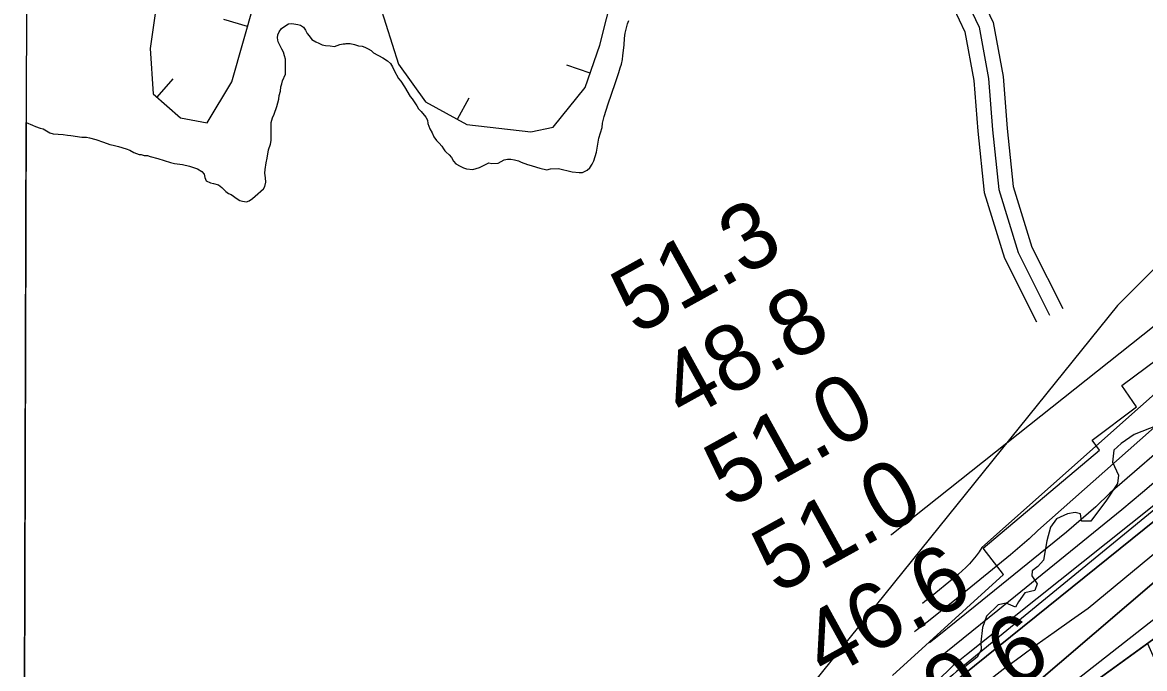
# Model space of a CAD drawing. Extents: x 3177385 to 3215275, y 903885 to 929304.
# Drawn here: x 3181603 to 3182745, y 910081 to 910738 of the extents above; entities that cross this region are included whole.
import ezdxf

# ---------------------------------------------------------------- set-up
doc = ezdxf.new("R2010")
doc.units = 0
for name, color, linetype in [('V-BORW-LINE', 7, 'Continuous'), ('V-GRID-FRAM', 7, 'Continuous'), ('V-RIVR-EDGE', 7, 'Continuous'), ('V-RIVR-RANG', 7, 'Continuous'), ('V-ROAD-CNTR', 7, 'Continuous'), ('V-RRAP-RVMT', 7, 'Continuous'), ('V-SITE-VEGE', 7, 'Continuous'), ('V-TOPO-DPTH', 7, 'Continuous'), ('V-TOPO-MAJR', 7, 'Continuous'), ('V-TOPO-MINR', 7, 'Continuous'), ('V-TOPO-WATR', 7, 'Continuous')]:
    doc.layers.add(name, color=color, linetype=linetype)

msp = doc.modelspace()

# ---------------------------------------------------------------- linework, layer by layer
at = {"layer": 'V-BORW-LINE'}
for p, q in [((3181832.4, 910734), (3181808.4, 910740.9)), ((3182180.7, 910686.3), (3182157.1, 910694.5)), ((3181740.4, 910661.9), (3181756.8, 910680.7)), ((3182045.9, 910639.5), (3182057.7, 910661.5))]:
    msp.add_line(p, q, dxfattribs=at)
for points in [[(3181742.7, 910778.1), (3181733.5, 910711.5)], [(3182190.6, 910714.8), (3182204.3, 910768.7)], [(3181816.3, 910677.6), (3181839.4, 910758.7)], [(3181966.5, 910756.7), (3181985.8, 910695.6)], [(3181733.5, 910711.5), (3181736.3, 910665.4)], [(3182175.7, 910671.8), (3182190.6, 910714.8)], [(3181985.8, 910695.6), (3182013.3, 910657.1)], [(3181791.3, 910635.8), (3181816.3, 910677.6)], [(3182143.2, 910631.6), (3182175.7, 910671.8)], [(3181736.3, 910665.4), (3181764.3, 910641)], [(3182013.3, 910657.1), (3182055.4, 910634.3)], [(3181764.3, 910641), (3181791.3, 910635.8)], [(3182055.4, 910634.3), (3182120.4, 910626.8)], [(3182120.4, 910626.8), (3182143.2, 910631.6)]]:
    msp.add_lwpolyline(points, dxfattribs=at)
at = {"layer": 'V-GRID-FRAM'}
msp.add_lwpolyline([(3181653.7, 927525.9), (3181603.5, 909337.1), (3212939.2, 909264.2), (3212973.6, 927453), (3181653.7, 927525.9)], dxfattribs=at)
at = {"layer": 'V-RIVR-EDGE'}
for points in [[(3182757.3, 910328.2), (3182734.2, 910319.1), (3182720.8, 910309.9), (3182713.4, 910302.9), (3182712, 910290.9), (3182718, 910277.5), (3182717, 910269.2), (3182705.9, 910252.2), (3182690.1, 910230.9), (3182680.4, 910231), (3182679.5, 910238.4), (3182674, 910239.8), (3182666.1, 910238.4), (3182655, 910233.3), (3182649, 910224.6)], [(3182649, 910224.6), (3182645.3, 910210.7), (3182642, 910191.3), (3182636, 910184.9), (3182630.4, 910180.3), (3182629.9, 910175.2), (3182635.5, 910167.3), (3182633.1, 910160.4), (3182623, 910158.1), (3182616.5, 910148.9), (3182613.2, 910143.4), (3182604, 910147.6), (3182595.7, 910145.7), (3182583.7, 910134.2), (3182579.9, 910122.7), (3182578.1, 910107.9), (3182578.5, 910100.1), (3182574.3, 910092.7), (3182557.2, 910078.9)]]:
    msp.add_lwpolyline(points, dxfattribs=at)
at = {"layer": 'V-ROAD-CNTR'}
for points in [[(3182465.1, 912073.3), (3182448.6, 911930.8), (3182431.1, 911826.4), (3182415.3, 911728.9), (3182410.1, 911644.8), (3182407.2, 911570.4), (3182383.2, 911504.1), (3182361.3, 911446.3), (3182341, 911383.3), (3182327.8, 911314.4), (3182322.3, 911236), (3182319.5, 911168.2), (3182337.7, 911105.3), (3182378.7, 911013.4), (3182433.5, 910931.2), (3182484.1, 910856.7), (3182532.9, 910789.7), (3182562, 910728.6), (3182571, 910679.1), (3182575.1, 910627.5), (3182581.5, 910565.1), (3182602.1, 910498.4), (3182634.6, 910433.6)], [(3182480, 912071.6), (3182463.4, 911928.7), (3182445.9, 911823.9), (3182430.3, 911727.3), (3182425, 911644.1), (3182422.1, 911567.5), (3182397.3, 911498.9), (3182375.5, 911441.4), (3182355.6, 911379.6), (3182342.7, 911312.5), (3182337.3, 911235.2), (3182334.6, 911170), (3182351.8, 911110.5), (3182391.9, 911020.7), (3182446, 910939.5), (3182496.3, 910865.3), (3182545.9, 910797.4), (3182576.4, 910733.3), (3182585.9, 910681.1), (3182590.1, 910628.9), (3182596.3, 910568.1), (3182616, 910504), (3182648, 910440.3)], [(3182494.9, 912069.8), (3182478.3, 911926.6), (3182460.7, 911821.5), (3182445.2, 911725.6), (3182440, 911643.3), (3182437, 911564.6), (3182411.3, 911493.7), (3182389.7, 911436.4), (3182370.1, 911375.9), (3182357.6, 911310.5), (3182352.3, 911234.3), (3182349.7, 911171.9), (3182366, 911115.7), (3182405.1, 911028), (3182458.4, 910947.9), (3182508.6, 910874), (3182558.8, 910805.1), (3182590.8, 910737.9), (3182600.8, 910683), (3182605, 910630.2), (3182611.1, 910571.1), (3182630, 910509.6), (3182661.4, 910447.1)]]:
    msp.add_lwpolyline(points, dxfattribs=at)
at = {"layer": 'V-RRAP-RVMT'}
for p, q in [((3182721.5, 910368.8), (3182794.8, 910423.3)), ((3182736.4, 910347.1), (3182721.5, 910368.8)), ((3182691.3, 910313.2), (3182736.4, 910347.1)), ((3182698.8, 910303.2), (3182691.3, 910313.2)), ((3182580.6, 910203.5), (3182698.8, 910303.2)), ((3182601.3, 910176.6), (3182580.6, 910203.5)), ((3182488.3, 910073.8), (3182601.3, 910176.6))]:
    msp.add_line(p, q, dxfattribs=at)
at = {"layer": 'V-SITE-VEGE'}
for p, q in [((3182218.8, 910736.7), (3182220, 910740.1)), ((3181863.3, 910725.5), (3181864.5, 910728.6)), ((3181864.5, 910728.6), (3181866.9, 910731.8)), ((3181866.9, 910731.8), (3181871.3, 910735)), ((3181871.3, 910735), (3181874, 910736.5)), ((3181874, 910736.5), (3181877.4, 910736.8)), ((3181877.4, 910736.8), (3181883.5, 910735.8)), ((3181883.5, 910735.8), (3181886.4, 910735.1)), ((3181886.4, 910735.1), (3181889.3, 910733.2)), ((3181889.3, 910733.2), (3181891.3, 910730.3)), ((3181891.3, 910730.3), (3181893, 910726.9)), ((3182216.4, 910727.2), (3182218.8, 910736.7)), ((3181862.9, 910722.3), (3181863.3, 910725.5)), ((3181863.4, 910718.2), (3181862.9, 910722.3)), ((3181867.1, 910710.7), (3181863.4, 910718.2)), ((3181893, 910726.9), (3181895.2, 910724.5)), ((3181895.2, 910724.5), (3181897.9, 910720.8)), ((3181897.9, 910720.8), (3181901.8, 910718.2)), ((3181901.8, 910718.2), (3181905, 910717)), ((3181905, 910717), (3181908.2, 910715.3)), ((3182215.3, 910714.8), (3182215.7, 910721.9)), ((3182215.7, 910721.9), (3182216.4, 910727.2)), ((3181868.8, 910707.7), (3181867.1, 910710.7)), ((3181869.8, 910704.1), (3181868.8, 910707.7)), ((3181908.2, 910715.3), (3181911.8, 910714.6)), ((3181911.8, 910714.6), (3181916.5, 910714.2)), ((3181916.5, 910714.2), (3181920.8, 910713.5)), ((3181920.8, 910713.5), (3181926.4, 910715.5)), ((3181926.4, 910715.5), (3181929.6, 910716.2)), ((3181929.6, 910716.2), (3181931.8, 910716.2)), ((3181931.8, 910716.2), (3181932.8, 910716.7)), ((3181932.8, 910716.7), (3181936.9, 910716.5)), ((3181936.9, 910716.5), (3181941, 910715.6)), ((3181941, 910715.6), (3181945.2, 910714.1)), ((3181945.2, 910714.1), (3181948.8, 910713.9)), ((3181948.8, 910713.9), (3181951.8, 910713)), ((3181951.8, 910713), (3181955.2, 910711.3)), ((3181955.2, 910711.3), (3181958.1, 910709.6)), ((3181958.1, 910709.6), (3181960.6, 910707.2)), ((3181960.6, 910707.2), (3181970.1, 910701.9)), ((3182213.9, 910704.3), (3182215.3, 910714.8)), ((3181871.1, 910700.5), (3181869.8, 910704.1)), ((3181871.1, 910692.2), (3181871.1, 910700.5)), ((3181970.1, 910701.9), (3181974.7, 910698.8)), ((3181974.7, 910698.8), (3181977.7, 910696.1)), ((3181977.7, 910696.1), (3181979.9, 910692.7)), ((3182211.3, 910691.9), (3182212.7, 910695.6)), ((3182212.7, 910695.6), (3182213.7, 910700.4)), ((3182213.7, 910700.4), (3182213.9, 910704.3)), ((3181868, 910678.5), (3181870.9, 910685.4)), ((3181870.9, 910685.4), (3181871.1, 910692.2)), ((3181979.9, 910692.7), (3181981.6, 910689.1)), ((3181981.6, 910689.1), (3181986, 910681.1)), ((3182206.3, 910676), (3182209.9, 910687)), ((3182209.9, 910687), (3182211.3, 910691.9)), ((3181865.9, 910668.1), (3181866.4, 910672.4)), ((3181866.4, 910672.4), (3181867.1, 910675.6)), ((3181867.1, 910675.6), (3181868, 910678.5)), ((3181986, 910681.1), (3181988.3, 910678.2)), ((3181988.3, 910678.2), (3181991.9, 910672.6)), ((3181991.9, 910672.6), (3181997.9, 910662.7)), ((3182199.2, 910655.3), (3182206.3, 910676)), ((3181862.1, 910652.5), (3181864.3, 910660)), ((3181864.3, 910660), (3181864.7, 910663.7)), ((3181864.7, 910663.7), (3181865.9, 910668.1)), ((3181997.9, 910662.7), (3181999.8, 910660.2)), ((3181999.8, 910660.2), (3182004.5, 910653.2)), ((3181859.3, 910644.7), (3181862.1, 910652.5)), ((3182004.5, 910653.2), (3182006.2, 910650.3)), ((3182006.2, 910650.3), (3182008.9, 910647.4)), ((3182195.1, 910642.4), (3182199.2, 910655.3)), ((3181856.4, 910636.4), (3181857.6, 910641)), ((3181857.6, 910641), (3181859.3, 910644.7)), ((3182008.9, 910647.4), (3182013.6, 910641.6)), ((3182013.6, 910641.6), (3182015.3, 910638.7)), ((3182015.3, 910638.7), (3182015.8, 910635.3)), ((3182193.5, 910635.6), (3182195.1, 910642.4)), ((3181603.6, 909387.1), (3181607.1, 910636.1)), ((3181607.1, 910636.1), (3181613.8, 910633.7)), ((3181613.8, 910633.7), (3181616.8, 910632.2)), ((3181616.8, 910632.2), (3181621.4, 910630.6)), ((3181621.4, 910630.6), (3181624.6, 910629.9)), ((3181624.6, 910629.9), (3181628, 910627.7)), ((3181628, 910627.7), (3181631.4, 910625.8)), ((3181631.4, 910625.8), (3181634.8, 910624.6)), ((3181856.3, 910618.1), (3181856.5, 910627.6)), ((3181856.5, 910627.6), (3181856.4, 910636.4)), ((3182015.8, 910635.3), (3182017.8, 910629.9)), ((3182017.8, 910629.9), (3182020, 910625.8)), ((3182020, 910625.8), (3182022, 910621.7)), ((3182189.7, 910620.2), (3182193, 910631.2)), ((3182193, 910631.2), (3182193.5, 910635.6)), ((3181634.8, 910624.6), (3181645, 910623.9)), ((3181645, 910623.9), (3181649.2, 910623.2)), ((3181649.2, 910623.2), (3181652.6, 910623)), ((3181652.6, 910623), (3181664, 910621.4)), ((3181664, 910621.4), (3181668.7, 910621.2)), ((3181668.7, 910621.2), (3181671.8, 910620.5)), ((3181671.8, 910620.5), (3181678.2, 910618.8)), ((3181678.2, 910618.8), (3181686, 910616.4)), ((3181686, 910616.4), (3181692.3, 910614)), ((3181853.7, 910608.4), (3181855.6, 910614.2)), ((3181855.6, 910614.2), (3181856.3, 910618.1)), ((3182022, 910621.7), (3182024.5, 910618.1)), ((3182024.5, 910618.1), (3182027.4, 910615.2)), ((3182027.4, 910615.2), (3182029.8, 910612.3)), ((3182187.8, 910610), (3182189.7, 910620.2)), ((3181692.3, 910614), (3181695.7, 910613.3)), ((3181695.7, 910613.3), (3181701.1, 910611.9)), ((3181701.1, 910611.9), (3181709.1, 910609.5)), ((3181709.1, 910609.5), (3181712.6, 910608.1)), ((3181712.6, 910608.1), (3181716.7, 910605.9)), ((3181716.7, 910605.9), (3181722.3, 910603.8)), ((3181722.3, 910603.8), (3181724.3, 910603.6)), ((3181724.3, 910603.6), (3181727.2, 910602.8)), ((3181727.2, 910602.8), (3181730.6, 910602.6)), ((3181852.5, 910600.1), (3181853.7, 910608.4)), ((3182029.8, 910612.3), (3182031.8, 910609.6)), ((3182031.8, 910609.6), (3182033, 910607.4)), ((3182033, 910607.4), (3182034.5, 910606.2)), ((3182034.5, 910606.2), (3182037.5, 910603.3)), ((3182037.5, 910603.3), (3182039.7, 910600.7)), ((3182184.5, 910597.3), (3182187.3, 910606.1)), ((3182187.3, 910606.1), (3182187.8, 910610)), ((3181730.6, 910602.6), (3181733.5, 910601.7)), ((3181733.5, 910601.7), (3181741.1, 910599.8)), ((3181741.1, 910599.8), (3181754, 910595.5)), ((3181754, 910595.5), (3181758.2, 910594.5)), ((3181758.2, 910594.5), (3181766.4, 910593.4)), ((3181766.4, 910593.4), (3181773.5, 910591.7)), ((3181773.5, 910591.7), (3181778.4, 910590.3)), ((3181850.2, 910588.4), (3181851.4, 910595.4)), ((3181851.4, 910595.4), (3181852.5, 910600.1)), ((3182039.7, 910600.7), (3182041.9, 910597)), ((3182041.9, 910597), (3182044.1, 910594.1)), ((3182044.1, 910594.1), (3182048.5, 910591.7)), ((3182048.5, 910591.7), (3182052.1, 910590)), ((3182068.4, 910590.6), (3182074.5, 910593.4)), ((3182074.5, 910593.4), (3182077.9, 910595.1)), ((3182077.9, 910595.1), (3182080.8, 910594.4)), ((3182080.8, 910594.4), (3182087.2, 910594.9)), ((3182087.2, 910594.9), (3182093.2, 910598.4)), ((3182093.2, 910598.4), (3182096.9, 910599.1)), ((3182096.9, 910599.1), (3182100, 910599.1)), ((3182100, 910599.1), (3182103.9, 910598.4)), ((3182103.9, 910598.4), (3182107.8, 910597.2)), ((3182107.8, 910597.2), (3182110.8, 910595.8)), ((3182110.8, 910595.8), (3182117.1, 910593.4)), ((3182117.1, 910593.4), (3182118.6, 910593.2)), ((3182118.6, 910593.2), (3182122, 910592.2)), ((3182122, 910592.2), (3182129.5, 910589.9)), ((3182180.6, 910590.2), (3182183, 910593.9)), ((3182183, 910593.9), (3182184.5, 910597.3)), ((3181778.4, 910590.3), (3181781.6, 910589.1)), ((3181781.6, 910589.1), (3181786, 910586.5)), ((3181786, 910586.5), (3181788.2, 910583.6)), ((3181788.2, 910583.6), (3181788.9, 910580.2)), ((3181788.9, 910580.2), (3181790.4, 910576.8)), ((3181850, 910584.7), (3181850.2, 910588.4)), ((3181850.7, 910580.1), (3181850, 910584.7)), ((3181851, 910575.5), (3181850.7, 910580.1)), ((3182052.1, 910590), (3182055.1, 910589.1)), ((3182055.1, 910589.1), (3182061.6, 910588.6)), ((3182061.6, 910588.6), (3182068.4, 910590.6)), ((3182129.5, 910589.9), (3182136.6, 910588.2)), ((3182136.6, 910588.2), (3182140.5, 910589)), ((3182140.5, 910589), (3182148.5, 910589.5)), ((3182148.5, 910589.5), (3182162.4, 910586.2)), ((3182162.4, 910586.2), (3182169.5, 910585.3)), ((3182169.5, 910585.3), (3182172.9, 910585.3)), ((3182172.9, 910585.3), (3182177.7, 910587.8)), ((3182177.7, 910587.8), (3182180.6, 910590.2)), ((3182857.8, 910591.1), (3182717, 910450.3)), ((3181790.4, 910576.8), (3181794.6, 910574.8)), ((3181794.6, 910574.8), (3181797.7, 910574.1)), ((3181797.7, 910574.1), (3181802.8, 910572.7)), ((3181802.8, 910572.7), (3181806.3, 910570.1)), ((3181806.3, 910570.1), (3181810.2, 910566)), ((3181840.1, 910561.5), (3181848.6, 910568.7)), ((3181848.6, 910568.7), (3181850.1, 910571.3)), ((3181850.1, 910571.3), (3181851, 910575.5)), ((3181810.2, 910566), (3181812.9, 910564)), ((3181812.9, 910564), (3181815.8, 910563.1)), ((3181815.8, 910563.1), (3181821.7, 910558.5)), ((3181821.7, 910558.5), (3181824.4, 910557)), ((3181834.1, 910556.6), (3181837.5, 910558.8)), ((3181837.5, 910558.8), (3181840.1, 910561.5)), ((3181824.4, 910557), (3181827.3, 910556.1)), ((3181827.3, 910556.1), (3181831.2, 910555.6)), ((3181831.2, 910555.6), (3181834.1, 910556.6)), ((3182717, 910450.3), (3182041.9, 909612.4))]:
    msp.add_line(p, q, dxfattribs=at)
at = {"layer": 'V-TOPO-DPTH'}
for points in [[(3183314.1, 910681.7), (3182559.3, 910073.9), (3182558, 910073), (3182554.4, 910069.8)], [(3182554.4, 910069.8), (3182558, 910073), (3182559.3, 910073.9), (3183314.1, 910681.7)], [(3181813.1, 909336.6), (3181847.7, 909336.5), (3182602.7, 910040.9), (3182622.9, 910056.3), (3183297.5, 910633.5)], [(3183297.5, 910633.5), (3182622.9, 910056.3), (3182602.7, 910040.9), (3181847.7, 909336.5), (3181885.9, 909336.4)], [(3181885.9, 909336.4), (3182605.7, 910003.9), (3182613.7, 910009.4), (3183374.9, 910561.1)], [(3182777.5, 910265.6), (3182563.4, 910094.8), (3182556.7, 910089.5), (3182550, 910084.1), (3181787.1, 909336.7), (3181813.1, 909336.6)], [(3181885.9, 909336.4), (3182605.7, 910003.9), (3182613.7, 910009.4), (3182747.7, 910106.6), (3182762.3, 910073.5)]]:
    msp.add_lwpolyline(points, dxfattribs=at)
at = {"layer": 'V-TOPO-MAJR'}
msp.add_lwpolyline([(3183258.4, 910772.7), (3182636, 910221.5), (3182627.1, 910212.9), (3182617.8, 910204.7), (3182608.4, 910196.7), (3182549.5, 910148.9), (3182537.2, 910139), (3182524.8, 910129.3), (3182512.3, 910119.7), (3182510.6, 910118.4)], dxfattribs=at)
at = {"layer": 'V-TOPO-MINR'}
for points in [[(3184745, 911681), (3184664.6, 911644.8), (3184584.5, 911608.1), (3184504.7, 911570.6), (3184425, 911532.7), (3184105.2, 911378.7), (3184075.2, 911363.9), (3184045.5, 911348.7), (3184016.1, 911332.9), (3183986.8, 911316.7), (3183398.7, 910920.7), (3183382.8, 910908.5), (3183366.4, 910896.9), (3183362.3, 910894.1), (3183347.6, 910884.2), (3183332.9, 910874.6), (3183318, 910865.1), (3183303.1, 910855.7), (3183288.1, 910846.4), (3183273.2, 910836.9), (3183258.4, 910827.4), (3183243.6, 910817.8), (3182487.6, 910217.2), (3182486.5, 910216.5)], [(3183227.6, 910780.8), (3182579.1, 910204), (3182576.3, 910199.6), (3182573.3, 910195.5), (3182570, 910191.5), (3182566.6, 910187.6), (3182562.9, 910183.9), (3182559.2, 910180.3), (3182555.4, 910176.9), (3182551.4, 910173.6), (3182526.5, 910153.3), (3182521.3, 910149.1), (3182518.8, 910147.2)], [(3183292.5, 910764.1), (3182709.2, 910259.2), (3182694.9, 910245.6), (3182680.2, 910232.4), (3182665.1, 910219.7), (3182572.5, 910144.4), (3182553.1, 910128.8), (3182533.7, 910113.3), (3182526, 910107.3)], [(3183299.8, 910736.3), (3182742.4, 910260.1), (3182721.6, 910242.5), (3182595.4, 910140), (3182569.1, 910118.6), (3182542.6, 910097.2), (3182526.9, 910084.6)], [(3183315.3, 910701.5), (3182561.5, 910084.3), (3182557.4, 910081.1), (3182553.4, 910077.9), (3182549.5, 910074.6), (3182545.7, 910071.3), (3181797.2, 909336.6)], [(3183341.9, 910683.5), (3182687.3, 910142), (3182670.3, 910130.1), (3182652.8, 910117.7), (3182635.4, 910105.3), (3182618.1, 910092.6), (3182600.9, 910079.9), (3182583.9, 910066.9), (3181830.4, 909336.6)], [(3183297.5, 910633.5), (3182622.9, 910056.3), (3182602.7, 910040.9), (3181847.7, 909336.5)], [(3183343.1, 910592.5), (3182616.1, 910022.6), (3182604.8, 910014.3), (3182593.7, 910005.7), (3181869, 909336.5)], [(3183374.9, 910561.1), (3182613.7, 910009.4), (3182605.7, 910003.9), (3181885.9, 909336.4)], [(3182777.5, 910265.6), (3182563.4, 910094.8), (3182556.7, 910089.5), (3182550, 910084.1), (3181787.1, 909336.7)]]:
    msp.add_lwpolyline(points, dxfattribs=at)
at = {"layer": 'V-TOPO-WATR'}
msp.add_lwpolyline([(3183314.1, 910681.7), (3182559.3, 910073.9), (3182558, 910073), (3182554.4, 910069.8)], dxfattribs=at)

# ---------------------------------------------------------------- texts
at = {"layer": 'V-RIVR-RANG'}
for s, rotation, p in [('51.3', 28.9383, (3182227.6, 910419.3)), ('48.8', 28.9383, (3182276.2, 910331.9)), ('51.0', 28.9383, (3182322.3, 910243.1)), ('51.0', 28.9383, (3182370.9, 910155.8)), ('46.6', 28.9383, (3182420.4, 910068.9)), ('10.6', 29.4133, (3182500.5, 909998.1))]:
    msp.add_text(s, height=67, rotation=rotation, dxfattribs=at).set_placement(p)

doc.saveas('drawing.dxf')
